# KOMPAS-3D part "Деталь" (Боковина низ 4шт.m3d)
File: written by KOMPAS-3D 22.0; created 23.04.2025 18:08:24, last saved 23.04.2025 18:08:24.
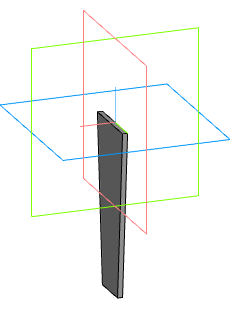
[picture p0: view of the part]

Document properties: Автор: Admin; Полное имя файла: D:\28.11.2016\3D модели\Абилимпикс\2025\Воронка квадратная\Боковина низ 4шт.m3d

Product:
- Part/product: Деталь
    Масса: 0.009457

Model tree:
1. Эскиз:1
2. Элемент выдавливания:1
     Расстояние 1 = 1.5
